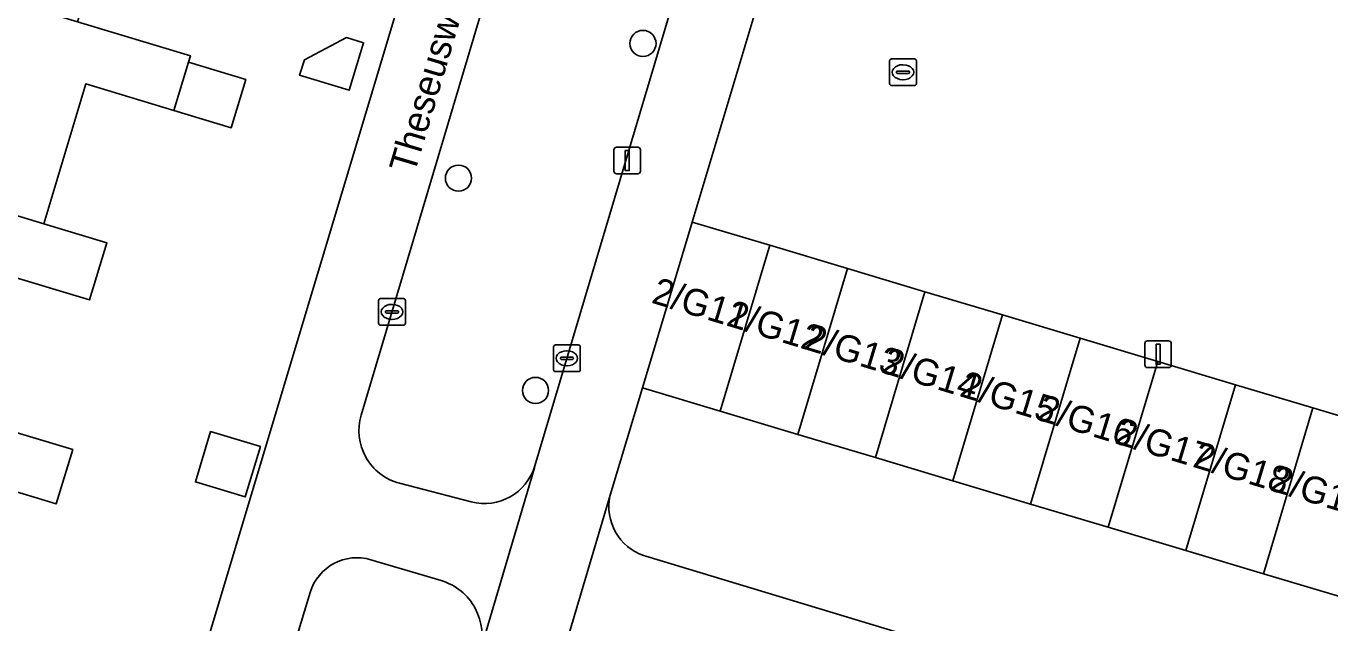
# Model space of a CAD drawing. Extents: x 162184 to 163154, y 385507 to 386516.
# Drawn here: x 162728.79 to 162777.62, y 386151.22 to 386173.56 of the extents above; entities that cross this region are included whole.
import ezdxf

# ---------------------------------------------------------------- set-up
doc = ezdxf.new("R2010")
doc.units = 0
for name, color, linetype in [('IMGEO_Boom', 7, 'Continuous'), ('IMGEO_Erf', 7, 'Continuous'), ('IMGEO_Groenvoorziening', 7, 'Continuous'), ('IMGEO_Kolk', 7, 'Continuous'), ('IMGEO_Lichtmast', 7, 'Continuous'), ('IMGEO_Openbare_ruimte_label', 7, 'Continuous'), ('IMGEO_Pand', 7, 'Continuous'), ('IMGEO_Pand_nummerreeks', 7, 'Continuous'), ('IMGEO_Parkeervlak_open', 7, 'Continuous'), ('IMGEO_Voetpad_open', 7, 'Continuous')]:
    doc.layers.add(name, color=color, linetype=linetype)

msp = doc.modelspace()

# ---------------------------------------------------------------- linework, layer by layer
at = {"layer": 'IMGEO_Boom'}
for centre in [(162751.893, 386172.914), (162744.982, 386167.872), (162747.869, 386159.924)]:
    msp.add_circle(centre, 0.489, dxfattribs=at)
at = {"layer": 'IMGEO_Erf'}
for points in [[(162731.855, 386138.123), (162747.552, 386190.45), (162747.619, 386190.716), (162747.661, 386190.986), (162747.68, 386191.259), (162747.674, 386191.533), (162747.643, 386191.805), (162747.588, 386192.074), (162747.51, 386192.336), (162747.408, 386192.59), (162747.284, 386192.835), (162747.139, 386193.067), (162746.974, 386193.285), (162746.789, 386193.488), (162746.588, 386193.673), (162746.37, 386193.84), (162746.139, 386193.986), (162745.895, 386194.111), (162745.642, 386194.214), (162745.506, 386194.259), (162725.062, 386200.438)], [(162728.142, 386198.74), (162740.665, 386194.969), (162741.658, 386194.67), (162739.422, 386187.278), (162738.805, 386185.229), (162735.535, 386186.208), (162733.932, 386180.882), (162736.214, 386180.195), (162735.589, 386178.119), (162732.336, 386179.099), (162730.718, 386173.725), (162734.944, 386172.452), (162734.871, 386172.211), (162737.018, 386171.565), (162736.474, 386169.757), (162734.327, 386170.403), (162731.022, 386171.398), (162729.447, 386166.166), (162731.813, 386165.454), (162731.169, 386163.313), (162727.884, 386164.302)], [(162726.285, 386158.99), (162730.533, 386157.711), (162729.92, 386155.677), (162726.607, 386156.674)]]:
    msp.add_lwpolyline(points, dxfattribs=at)
for points in [[(162740.785, 386173.133), (162741.429, 386172.939), (162740.894, 386171.162), (162739.035, 386171.722), (162739.211, 386172.306)], [(162737.562, 386157.824), (162736.996, 386155.941), (162735.131, 386156.502), (162735.697, 386158.385)]]:
    msp.add_lwpolyline(points, close=True, dxfattribs=at)
at = {"layer": 'IMGEO_Groenvoorziening'}
for points in [[(162750.76, 386190.615), (162741.339, 386159.002)], [(162747.844, 386157.099), (162757.217, 386188.564)], [(162778.038, 386152.193), (162775.131, 386153.062), (162772.225, 386153.932), (162769.318, 386154.802), (162766.411, 386155.671), (162763.505, 386156.541), (162760.598, 386157.41), (162757.691, 386158.28), (162754.785, 386159.15), (162751.879, 386160.019), (162750.699, 386156.134), (162750.657, 386155.965), (162750.629, 386155.794), (162750.617, 386155.62), (162750.621, 386155.447), (162750.64, 386155.274), (162750.675, 386155.104), (162750.725, 386154.937), (162750.789, 386154.776), (162750.868, 386154.621), (162750.96, 386154.473), (162751.064, 386154.334), (162751.181, 386154.206), (162751.309, 386154.088), (162751.447, 386153.982), (162751.594, 386153.889), (162751.748, 386153.809), (162751.909, 386153.744), (162751.997, 386153.715), (162779.405, 386145.432)], [(162742.772, 386156.454), (162745.456, 386155.754)], [(162744.341, 386152.804), (162741.707, 386153.587)], [(162739.429, 386152.362), (162732.559, 386129.74)]]:
    msp.add_lwpolyline(points, dxfattribs=at)
for centre, radius, start, end in [((162743.284, 386158.419), 2.031, 163.3163, 255.3907), ((162745.954, 386157.662), 1.972, 255.3735, 343.4058), ((162741.183, 386151.831), 1.832, 73.3805, 163.158), ((162743.729, 386150.756), 2.137, 343.2082, 73.36)]:
    msp.add_arc(centre, radius, start, end, dxfattribs=at)
at = {"layer": 'IMGEO_Kolk'}
for p, q in [((162761.132, 386171.412), (162761.132, 386172.264)), ((162761.207, 386172.338), (162762.059, 386172.338)), ((162761.434, 386171.881), (162761.832, 386171.881)), ((162761.62, 386172.118), (162761.645, 386172.118)), ((162762.133, 386172.264), (162762.133, 386171.412)), ((162761.391, 386171.832), (162761.391, 386171.844)), ((162761.829, 386171.795), (162761.431, 386171.795)), ((162761.643, 386171.558), (162761.618, 386171.558)), ((162761.875, 386171.844), (162761.875, 386171.832)), ((162762.059, 386171.338), (162761.207, 386171.338)), ((162741.993, 386162.439), (162741.993, 386163.291)), ((162742.068, 386163.365), (162742.92, 386163.365)), ((162742.481, 386163.145), (162742.506, 386163.145)), ((162742.994, 386163.291), (162742.994, 386162.439)), ((162742.252, 386162.859), (162742.252, 386162.871)), ((162742.69, 386162.822), (162742.292, 386162.822)), ((162742.295, 386162.908), (162742.693, 386162.908)), ((162742.736, 386162.871), (162742.736, 386162.859)), ((162742.92, 386162.365), (162742.068, 386162.365)), ((162742.504, 386162.585), (162742.479, 386162.585)), ((162748.619, 386161.628), (162749.471, 386161.628)), ((162748.544, 386160.702), (162748.544, 386161.554)), ((162748.803, 386161.122), (162748.803, 386161.134)), ((162748.846, 386161.171), (162749.244, 386161.171)), ((162749.032, 386161.408), (162749.057, 386161.408)), ((162749.287, 386161.134), (162749.287, 386161.122)), ((162749.545, 386161.554), (162749.545, 386160.702)), ((162749.241, 386161.085), (162748.843, 386161.085)), ((162749.055, 386160.848), (162749.03, 386160.848)), ((162749.471, 386160.628), (162748.619, 386160.628))]:
    msp.add_line(p, q, dxfattribs=at)
for points in [[(162761.132, 386171.412), (162761.132, 386172.264)], [(162761.207, 386172.338), (162762.059, 386172.338)], [(162762.133, 386172.264), (162762.133, 386171.412)], [(162762.059, 386171.338), (162761.207, 386171.338)], [(162741.993, 386162.439), (162741.993, 386163.291)], [(162742.068, 386163.365), (162742.92, 386163.365)], [(162742.994, 386163.291), (162742.994, 386162.439)], [(162742.92, 386162.365), (162742.068, 386162.365)], [(162748.619, 386161.628), (162749.471, 386161.628)], [(162748.544, 386160.702), (162748.544, 386161.554)], [(162749.545, 386161.554), (162749.545, 386160.702)], [(162749.471, 386160.628), (162748.619, 386160.628)]]:
    msp.add_lwpolyline(points, dxfattribs=at)
for centre, radius, start, end in [((162761.209, 386172.262), 0.0765, 91.552, 178.448), ((162761.209, 386172.262), 0.0765, 91.552, 178.448), ((162761.431, 386171.841), 0.0403, 85.8775, 175.7526), ((162761.836, 386171.843), 0.0386, 1.7309, 96.639), ((162762.057, 386172.262), 0.0765, 1.552, 88.448), ((162762.057, 386172.262), 0.0765, 1.552, 88.448), ((162761.209, 386171.414), 0.0765, 181.552, 268.448), ((162761.209, 386171.414), 0.0765, 181.552, 268.448), ((162761.428, 386171.831), 0.0366, 178.938, 274.7102), ((162761.832, 386171.838), 0.043, 264.8664, 352.4533), ((162762.057, 386171.414), 0.0765, 271.552, 358.448), ((162762.057, 386171.414), 0.0765, 271.552, 358.448), ((162742.07, 386163.289), 0.0765, 91.552, 178.448), ((162742.07, 386163.289), 0.0765, 91.552, 178.448), ((162742.918, 386163.289), 0.0765, 1.552, 88.448), ((162742.918, 386163.289), 0.0765, 1.552, 88.448), ((162742.292, 386162.868), 0.0403, 85.8775, 175.7526), ((162742.289, 386162.858), 0.0366, 178.938, 274.7102), ((162742.693, 386162.865), 0.043, 264.8664, 352.4533), ((162742.697, 386162.87), 0.0386, 1.7309, 96.639), ((162742.07, 386162.441), 0.0765, 181.552, 268.448), ((162742.07, 386162.441), 0.0765, 181.552, 268.448), ((162742.918, 386162.441), 0.0765, 271.552, 358.448), ((162742.918, 386162.441), 0.0765, 271.552, 358.448), ((162748.621, 386161.552), 0.0765, 91.552, 178.448), ((162748.621, 386161.552), 0.0765, 91.552, 178.448), ((162749.469, 386161.552), 0.0765, 1.552, 88.448), ((162749.469, 386161.552), 0.0765, 1.552, 88.448), ((162748.843, 386161.131), 0.0403, 85.8775, 175.7526), ((162749.248, 386161.133), 0.0386, 1.7309, 96.639), ((162748.621, 386160.704), 0.0765, 181.552, 268.448), ((162748.621, 386160.704), 0.0765, 181.552, 268.448), ((162748.84, 386161.121), 0.0366, 178.938, 274.7102), ((162749.244, 386161.128), 0.043, 264.8664, 352.4533), ((162749.469, 386160.704), 0.0765, 271.552, 358.448), ((162749.469, 386160.704), 0.0765, 271.552, 358.448)]:
    msp.add_arc(centre, radius, start, end, dxfattribs=at)
for centre, major_axis, ratio, start_param, end_param in [((162761.619, 386171.838), (-0.387, 0.002), 0.722429, 4.712389, 7.853982), ((162761.644, 386171.838), (-0.39, 0.002), 0.717154, 1.570796, 4.712389), ((162742.48, 386162.865), (-0.387, 0.002), 0.722429, 4.712389, 7.853982), ((162742.505, 386162.865), (-0.39, 0.002), 0.717154, 1.570796, 4.712389), ((162749.031, 386161.128), (-0.387, 0.002), 0.722429, 4.712389, 7.853982), ((162749.056, 386161.128), (-0.39, 0.002), 0.717154, 1.570796, 4.712389)]:
    msp.add_ellipse(centre, major_axis=major_axis, ratio=ratio, start_param=start_param, end_param=end_param, dxfattribs=at)
at = {"layer": 'IMGEO_Lichtmast'}
for p, q in [((162750.908, 386169.033), (162751.698, 386169.033)), ((162751.698, 386169.033), (162750.908, 386169.033)), ((162750.808, 386168.133), (162750.808, 386168.933)), ((162750.808, 386168.933), (162750.808, 386168.133)), ((162751.798, 386168.933), (162751.798, 386168.133)), ((162751.798, 386168.133), (162751.798, 386168.933)), ((162751.698, 386168.033), (162750.908, 386168.033)), ((162750.908, 386168.033), (162751.698, 386168.033)), ((162770.692, 386160.881), (162770.692, 386161.681)), ((162770.692, 386161.681), (162770.692, 386160.881)), ((162770.792, 386161.781), (162771.582, 386161.781)), ((162771.582, 386161.781), (162770.792, 386161.781)), ((162771.682, 386161.681), (162771.682, 386160.881)), ((162771.682, 386160.881), (162771.682, 386161.681)), ((162771.582, 386160.781), (162770.792, 386160.781)), ((162770.792, 386160.781), (162771.582, 386160.781))]:
    msp.add_line(p, q, dxfattribs=at)
for points in [[(162751.228, 386168.908), (162751.378, 386168.908), (162751.378, 386168.158), (162751.228, 386168.158), (162751.228, 386168.908)], [(162771.112, 386161.656), (162771.262, 386161.656), (162771.262, 386160.906), (162771.112, 386160.906), (162771.112, 386161.656)]]:
    msp.add_lwpolyline(points, dxfattribs=at)
for centre, start, end in [((162750.908, 386168.933), 90, 180), ((162750.908, 386168.933), 90, 180), ((162751.698, 386168.933), 0, 90), ((162751.698, 386168.933), 360, 90), ((162750.908, 386168.133), 180, 270), ((162750.908, 386168.133), 180, 270), ((162751.698, 386168.133), 270, 0), ((162751.698, 386168.133), 270, 0), ((162770.792, 386161.681), 90, 180), ((162770.792, 386161.681), 90, 180), ((162771.582, 386161.681), 0, 90), ((162771.582, 386161.681), 360, 90), ((162770.792, 386160.881), 180, 270), ((162770.792, 386160.881), 180, 270), ((162771.582, 386160.881), 270, 0), ((162771.582, 386160.881), 270, 0)]:
    msp.add_arc(centre, 0.1, start, end, dxfattribs=at)
at = {"layer": 'IMGEO_Pand'}
for points in [[(162734.871, 386172.211), (162734.944, 386172.452), (162730.718, 386173.725), (162722.473, 386176.205), (162722.438, 386176.087), (162723.594, 386175.739), (162722.817, 386173.158), (162721.667, 386173.504), (162721.589, 386173.246), (162722.729, 386172.903), (162721.639, 386169.28), (162721.411, 386169.348), (162721.206, 386168.668), (162729.447, 386166.166), (162731.022, 386171.398), (162734.327, 386170.403)], [(162739.211, 386172.306), (162739.035, 386171.722), (162740.894, 386171.162), (162741.429, 386172.939), (162740.785, 386173.133)], [(162734.871, 386172.211), (162734.327, 386170.403), (162736.474, 386169.757), (162737.018, 386171.565)], [(162726.285, 386158.99), (162727.884, 386164.302), (162731.169, 386163.313), (162731.813, 386165.454), (162729.447, 386166.166), (162721.206, 386168.668), (162719.279, 386169.248), (162719.2, 386168.986), (162720.403, 386168.624), (162719.629, 386166.055), (162718.447, 386166.411), (162718.378, 386166.182), (162719.577, 386165.821), (162718.488, 386162.202), (162718.289, 386162.262), (162718.05, 386161.466)], [(162753.736, 386166.228), (162751.879, 386160.019), (162754.785, 386159.15), (162756.643, 386165.358)], [(162756.643, 386165.358), (162754.785, 386159.15), (162757.691, 386158.28), (162759.549, 386164.489)], [(162759.549, 386164.489), (162757.691, 386158.28), (162760.598, 386157.41), (162762.456, 386163.619)], [(162762.456, 386163.619), (162760.598, 386157.41), (162763.505, 386156.541), (162765.362, 386162.749)], [(162765.362, 386162.749), (162763.505, 386156.541), (162766.411, 386155.671), (162768.269, 386161.879)], [(162768.269, 386161.879), (162766.411, 386155.671), (162769.318, 386154.802), (162771.176, 386161.01)], [(162730.533, 386157.711), (162726.285, 386158.99), (162718.05, 386161.466), (162718.013, 386161.343), (162719.127, 386161.007), (162718.339, 386158.391), (162717.213, 386158.73), (162717.146, 386158.508), (162718.283, 386158.165), (162717.174, 386154.482), (162716.947, 386154.551), (162716.745, 386153.878), (162725.007, 386151.359), (162726.607, 386156.674), (162729.92, 386155.677)], [(162771.176, 386161.01), (162769.318, 386154.802), (162772.225, 386153.932), (162774.082, 386160.14)], [(162774.082, 386160.14), (162772.225, 386153.932), (162775.131, 386153.062), (162776.989, 386159.27)], [(162776.989, 386159.27), (162775.131, 386153.062), (162778.038, 386152.193), (162779.895, 386158.401)], [(162735.131, 386156.502), (162736.996, 386155.941), (162737.562, 386157.824), (162735.697, 386158.385)]]:
    msp.add_lwpolyline(points, close=True, dxfattribs=at)
at = {"layer": 'IMGEO_Parkeervlak_open'}
msp.add_lwpolyline([(162785.222, 386156.813), (162789.567, 386171.119), (162787.107, 386171.876), (162784.2, 386172.748), (162781.293, 386173.619), (162778.387, 386174.491), (162775.48, 386175.362), (162772.573, 386176.234), (162769.667, 386177.105), (162766.76, 386177.977), (162763.853, 386178.848), (162760.947, 386179.72), (162758.04, 386180.591), (162753.736, 386166.228), (162756.643, 386165.358), (162759.549, 386164.489), (162762.456, 386163.619), (162765.362, 386162.749), (162768.269, 386161.879), (162771.176, 386161.01), (162774.082, 386160.14), (162776.989, 386159.27), (162779.895, 386158.401), (162782.802, 386157.531)], close=True, dxfattribs=at)
at = {"layer": 'IMGEO_Voetpad_open'}
for points in [[(162753.06, 386191.901), (162745.642, 386194.214), (162745.895, 386194.111), (162746.139, 386193.986), (162746.37, 386193.84), (162746.588, 386193.673), (162746.789, 386193.488), (162746.974, 386193.285), (162747.139, 386193.067), (162747.284, 386192.835), (162747.408, 386192.59), (162747.51, 386192.336), (162747.588, 386192.074), (162747.643, 386191.805), (162747.674, 386191.533), (162747.68, 386191.259), (162747.661, 386190.986), (162747.619, 386190.716), (162747.552, 386190.45), (162731.855, 386138.123)], [(162741.339, 386159.002), (162750.76, 386190.615)], [(162757.217, 386188.564), (162747.844, 386157.099), (162747.828, 386157.024), (162745.815, 386150.242), (162745.775, 386150.139), (162742.241, 386138.459), (162739.071, 386127.769), (162739.041, 386127.618), (162735.989, 386117.426), (162735.486, 386115.734), (162730.41, 386098.664), (162727.044, 386087.256)], [(162727.023, 386086.818), (162729.962, 386086.464), (162748.726, 386149.462), (162748.746, 386149.525), (162750.699, 386156.134), (162751.879, 386160.019), (162753.736, 386166.228), (162758.04, 386180.591)], [(162745.775, 386150.139), (162745.815, 386150.242), (162747.828, 386157.024), (162747.844, 386157.099)], [(162745.456, 386155.754), (162742.772, 386156.454)], [(162779.405, 386145.432), (162751.997, 386153.715), (162751.909, 386153.744), (162751.748, 386153.809), (162751.594, 386153.889), (162751.447, 386153.982), (162751.309, 386154.088), (162751.181, 386154.206), (162751.064, 386154.334), (162750.96, 386154.473), (162750.868, 386154.621), (162750.789, 386154.776), (162750.725, 386154.937), (162750.675, 386155.104), (162750.64, 386155.274), (162750.621, 386155.447), (162750.617, 386155.62), (162750.629, 386155.794), (162750.657, 386155.965), (162750.699, 386156.134), (162748.746, 386149.525)], [(162741.707, 386153.587), (162744.341, 386152.804)], [(162732.559, 386129.74), (162739.429, 386152.362)]]:
    msp.add_lwpolyline(points, dxfattribs=at)
for centre, radius, start, end in [((162743.284, 386158.419), 2.031, 163.3163, 255.3907), ((162745.954, 386157.662), 1.972, 255.3735, 343.4058), ((162741.183, 386151.831), 1.832, 73.3805, 163.158), ((162743.729, 386150.756), 2.137, 343.2082, 73.36)]:
    msp.add_arc(centre, radius, start, end, dxfattribs=at)

# ---------------------------------------------------------------- texts
at = {"layer": 'IMGEO_Openbare_ruimte_label'}
msp.add_text('Theseusweg', height=1, rotation=73.4325, dxfattribs=at).set_placement((162743.332, 386167.998))
at = {"layer": 'IMGEO_Pand_nummerreeks'}
for s, p in [('2/G11', (162752.172, 386163.217)), ('2/G12', (162754.97, 386162.369)), ('2/G13', (162757.887, 386161.485)), ('2/G14', (162760.797, 386160.603)), ('2/G15', (162763.708, 386159.722)), ('2/G16', (162766.618, 386158.84)), ('2/G17', (162769.529, 386157.958)), ('2/G18', (162772.442, 386157.075)), ('2/G19', (162775.346, 386156.195))]:
    msp.add_text(s, height=1, rotation=343.1416, dxfattribs=at).set_placement(p)

doc.saveas('drawing.dxf')
